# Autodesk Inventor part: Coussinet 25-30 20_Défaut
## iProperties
Shininess: 64.0
Length Units: 11269
Angle Units: 11279
Time Units: 11290
Mass Units: 11283
Length Display Precision: 3
Angle Display Precision: 2
Compacted: True
Part Number: Coussinet 25-30 20_Défaut
Document SubType Name: Modeling
Created: 2006-11
Material: Par défaut
Designer: profs_sti
Density: 0.0
Volumn: 0.0
Area: 0.0
PropertySet Name: Model Information
Control State: 0
Master: False
Checked Out: False
Author: profs_sti
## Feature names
1. Base1
